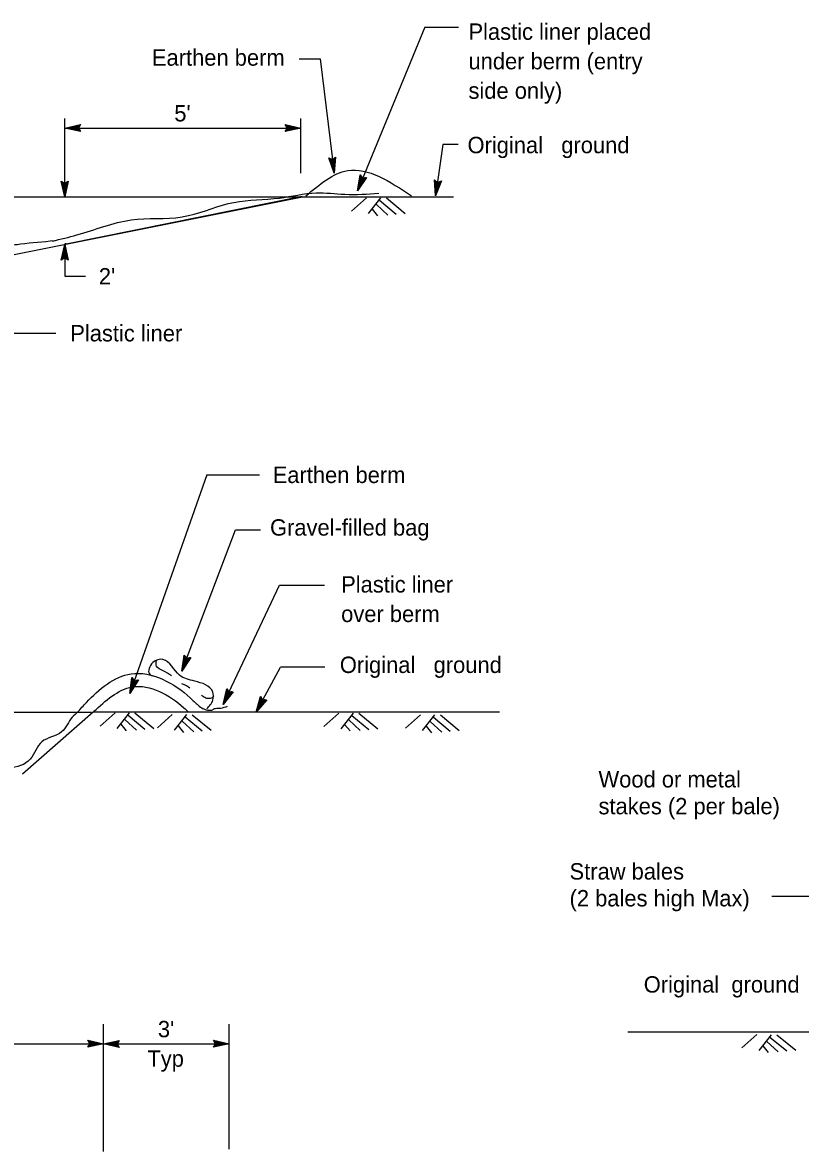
# Model space of a CAD drawing. Extents: x 6708826 to 6711089, y 1868571 to 1869537.
# Drawn here: x 6709143.3 to 6709428.3, y 1869105.8 to 1869519.2 of the extents above; entities that cross this region are included whole.
import ezdxf

# ---------------------------------------------------------------- set-up
doc = ezdxf.new("R2010")
doc.units = 0
for name, color, linetype in [('1 Control', 7, 'Continuous'), ('56 Stg 3 Anno', 7, 'Continuous'), ('57 Undefined', 7, 'Continuous'), ('59 Soundwall Ann', 7, 'Continuous'), ('60 Nongeo Data', 7, 'Continuous')]:
    doc.layers.add(name, color=color, linetype=linetype)

msp = doc.modelspace()

# ---------------------------------------------------------------- linework, layer by layer
at = {"layer": '1 Control'}
for p, q in [((6709267.01, 1869463.37), (6709267.01, 1869463.37)), ((6709269.37, 1869462.4), (6709269.37, 1869462.4)), ((6709265.99, 1869457.56), (6709265.99, 1869457.56)), ((6709202.56, 1869287.55), (6709202.56, 1869287.55)), ((6709204.96, 1869286.64), (6709204.96, 1869286.64)), ((6709183.36, 1869279.3), (6709183.36, 1869279.3)), ((6709201.71, 1869281.71), (6709201.71, 1869281.71)), ((6709185.77, 1869278.45), (6709185.77, 1869278.45)), ((6709218.15, 1869275.23), (6709218.15, 1869275.23)), ((6709182.65, 1869273.45), (6709182.65, 1869273.45)), ((6709220.47, 1869274.13), (6709220.47, 1869274.13)), ((6709230.52, 1869272.38), (6709230.52, 1869272.38)), ((6709232.77, 1869271.16), (6709232.77, 1869271.16)), ((6709216.84, 1869269.47), (6709216.84, 1869269.47)), ((6709228.89, 1869266.71), (6709228.89, 1869266.71))]:
    msp.add_line(p, q, dxfattribs=at)
for points in [[(6709269.37, 1869462.4), (6709265.99, 1869457.56), (6709267, 1869463.38), (6709267.24, 1869463.06), (6709266.49, 1869458.8), (6709268.98, 1869462.34), (6709268.59, 1869462.28), (6709267, 1869460.01), (6709267.48, 1869462.74), (6709267.71, 1869462.42), (6709267.51, 1869461.24), (6709268.2, 1869462.22), (6709267.89, 1869462.18), (6709267, 1869463.38), (6709267.89, 1869462.18)], [(6709204.96, 1869286.64), (6709201.71, 1869281.71), (6709202.56, 1869287.55), (6709202.81, 1869287.24), (6709202.18, 1869282.96), (6709204.57, 1869286.57), (6709204.18, 1869286.5), (6709202.65, 1869284.19), (6709203.05, 1869286.92), (6709203.3, 1869286.61), (6709203.13, 1869285.43), (6709203.79, 1869286.43), (6709203.48, 1869286.38), (6709202.56, 1869287.55), (6709203.48, 1869286.38)], [(6709185.77, 1869278.45), (6709182.65, 1869273.45), (6709183.35, 1869279.3), (6709183.61, 1869279), (6709183.09, 1869274.71), (6709185.38, 1869278.37), (6709185, 1869278.29), (6709183.53, 1869275.95), (6709183.86, 1869278.69), (6709184.11, 1869278.38), (6709183.97, 1869277.2), (6709184.61, 1869278.22), (6709184.3, 1869278.15), (6709183.35, 1869279.3), (6709184.3, 1869278.15)], [(6709220.47, 1869274.13), (6709216.84, 1869269.47), (6709218.15, 1869275.23), (6709218.37, 1869274.9), (6709217.41, 1869270.68), (6709220.07, 1869274.1), (6709219.68, 1869274.06), (6709217.98, 1869271.87), (6709218.59, 1869274.57), (6709218.81, 1869274.24), (6709218.55, 1869273.07), (6709219.28, 1869274.02), (6709218.98, 1869273.99), (6709218.15, 1869275.23), (6709218.98, 1869273.99)], [(6709232.77, 1869271.16), (6709228.89, 1869266.71), (6709230.52, 1869272.38), (6709230.72, 1869272.04), (6709229.53, 1869267.88), (6709232.37, 1869271.14), (6709231.98, 1869271.12), (6709230.16, 1869269.04), (6709230.92, 1869271.7), (6709231.12, 1869271.35), (6709230.79, 1869270.2), (6709231.58, 1869271.11), (6709231.27, 1869271.1), (6709230.52, 1869272.38), (6709231.27, 1869271.1)]]:
    msp.add_lwpolyline(points, close=True, dxfattribs=at)
msp.add_spline([(6709209.29, 1869267.99), (6709211.08, 1869267.44), (6709212.61, 1869267.44), (6709213.63, 1869267.95), (6709215.32, 1869268.12), (6709217.86, 1869268.63), (6709218.37, 1869268.8)], degree=3, dxfattribs=at)
at = {"layer": '56 Stg 3 Anno'}
for p, q in [((6709290.72, 1869517.49), (6709265.99, 1869457.56)), ((6709290.72, 1869517.49), (6709302.98, 1869517.49)), ((6709244.61, 1869505.89), (6709252.38, 1869505.89)), ((6709252.38, 1869505.89), (6709257.43, 1869464.09)), ((6709158.78, 1869455.4), (6709158.78, 1869484.01)), ((6709158.78, 1869480.58), (6709164.54, 1869481.86)), ((6709164.54, 1869481.86), (6709163.78, 1869480.58)), ((6709164.54, 1869481.86), (6709164.54, 1869481.86)), ((6709240.33, 1869480.58), (6709239.56, 1869481.87)), ((6709239.56, 1869481.87), (6709239.56, 1869481.87)), ((6709239.56, 1869481.87), (6709245.32, 1869480.58)), ((6709245.32, 1869464.09), (6709245.32, 1869484.01)), ((6709158.78, 1869480.58), (6709245.32, 1869480.58)), ((6709164.54, 1869479.29), (6709158.78, 1869480.58)), ((6709158.78, 1869480.58), (6709158.78, 1869480.58)), ((6709164.34, 1869479.64), (6709160.11, 1869480.58)), ((6709160.12, 1869480.58), (6709164.32, 1869481.51)), ((6709161.44, 1869480.58), (6709164.15, 1869481.18)), ((6709164.11, 1869479.98), (6709161.44, 1869480.58)), ((6709162.76, 1869480.58), (6709163.92, 1869480.83)), ((6709163.94, 1869480.31), (6709162.76, 1869480.58)), ((6709163.78, 1869480.58), (6709164.54, 1869479.29)), ((6709164.54, 1869479.29), (6709164.54, 1869479.29)), ((6709245.32, 1869480.58), (6709239.56, 1869479.3)), ((6709239.56, 1869479.3), (6709240.33, 1869480.58)), ((6709239.56, 1869479.3), (6709239.56, 1869479.3)), ((6709239.77, 1869481.52), (6709243.99, 1869480.58)), ((6709243.98, 1869480.58), (6709239.78, 1869479.65)), ((6709242.67, 1869480.58), (6709239.95, 1869479.98)), ((6709239.99, 1869481.18), (6709242.67, 1869480.58)), ((6709240.16, 1869480.85), (6709241.34, 1869480.58)), ((6709241.34, 1869480.58), (6709240.18, 1869480.33)), ((6709245.32, 1869480.58), (6709245.32, 1869480.58)), ((6709297.29, 1869474.56), (6709294.59, 1869455.69)), ((6709302.88, 1869474.56), (6709297.29, 1869474.56)), ((6709257.43, 1869464.09), (6709255.47, 1869469.65)), ((6709255.47, 1869469.65), (6709255.47, 1869469.65)), ((6709255.47, 1869469.65), (6709256.83, 1869469.04)), ((6709257.26, 1869465.41), (6709255.84, 1869469.47)), ((6709257.11, 1869466.72), (6709256.19, 1869469.34)), ((6709256.83, 1869469.04), (6709258.01, 1869469.96)), ((6709257.38, 1869469.45), (6709257.11, 1869466.72)), ((6709257.7, 1869469.71), (6709257.27, 1869465.4)), ((6709258.01, 1869469.96), (6709257.43, 1869464.09)), ((6709258.01, 1869469.96), (6709258.01, 1869469.96)), ((6709256.95, 1869468.04), (6709256.56, 1869469.16)), ((6709257.07, 1869469.24), (6709256.95, 1869468.04)), ((6709158.78, 1869455.4), (6709157.51, 1869461.16)), ((6709157.51, 1869461.16), (6709157.51, 1869461.16)), ((6709157.51, 1869461.16), (6709158.78, 1869460.39)), ((6709158.78, 1869460.39), (6709160.07, 1869461.16)), ((6709160.07, 1869461.16), (6709158.78, 1869455.4)), ((6709160.07, 1869461.16), (6709160.07, 1869461.16)), ((6709257.43, 1869464.09), (6709257.43, 1869464.09)), ((6709294.59, 1869455.69), (6709294.2, 1869461.57)), ((6709294.2, 1869461.57), (6709294.2, 1869461.57)), ((6709294.2, 1869461.57), (6709295.34, 1869460.62)), ((6709294.79, 1869457.01), (6709294.5, 1869461.3)), ((6709296.73, 1869461.18), (6709294.59, 1869455.69)), ((6709296.36, 1869461.03), (6709294.79, 1869456.99)), ((6709294.99, 1869458.31), (6709294.81, 1869461.08)), ((6709295.34, 1869460.62), (6709296.73, 1869461.18)), ((6709296.73, 1869461.18), (6709296.73, 1869461.18)), ((6709158.78, 1869456.74), (6709157.85, 1869460.94)), ((6709158.79, 1869458.05), (6709158.18, 1869460.77)), ((6709158.79, 1869459.38), (6709158.53, 1869460.54)), ((6709159.73, 1869460.95), (6709158.78, 1869456.73)), ((6709159.38, 1869460.73), (6709158.79, 1869458.05)), ((6709159.05, 1869460.56), (6709158.79, 1869459.38)), ((6709295.99, 1869460.86), (6709294.99, 1869458.31)), ((6709295.19, 1869459.62), (6709295.11, 1869460.8)), ((6709295.63, 1869460.74), (6709295.19, 1869459.62)), ((6709158.78, 1869455.4), (6709158.78, 1869455.4)), ((6709294.59, 1869455.69), (6709294.59, 1869455.69)), ((6709157.5, 1869432.22), (6709158.78, 1869437.98)), ((6709157.84, 1869432.42), (6709158.78, 1869436.65)), ((6709158.78, 1869437.98), (6709158.78, 1869426.29)), ((6709158.78, 1869437.98), (6709158.78, 1869437.98)), ((6709158.78, 1869437.98), (6709160.06, 1869432.22)), ((6709158.79, 1869436.64), (6709159.72, 1869432.44)), ((6709158.78, 1869432.98), (6709157.5, 1869432.22)), ((6709157.5, 1869432.22), (6709157.5, 1869432.22)), ((6709158.18, 1869432.65), (6709158.78, 1869435.32)), ((6709158.52, 1869432.82), (6709158.78, 1869434)), ((6709158.78, 1869435.32), (6709159.38, 1869432.61)), ((6709158.78, 1869434), (6709159.04, 1869432.84)), ((6709160.06, 1869432.22), (6709158.78, 1869432.98)), ((6709160.06, 1869432.22), (6709160.06, 1869432.22)), ((6709158.78, 1869426.29), (6709166.42, 1869426.29)), ((6709127.18, 1869405.43), (6709155.5, 1869405.43)), ((6709210.84, 1869353.56), (6709182.65, 1869273.45)), ((6709210.84, 1869353.56), (6709230.11, 1869353.56)), ((6709201.71, 1869281.71), (6709221.36, 1869333.46)), ((6709221.36, 1869333.46), (6709230.52, 1869333.46)), ((6709216.84, 1869269.47), (6709237.5, 1869313.21)), ((6709237.5, 1869313.21), (6709253.96, 1869313.21)), ((6709228.89, 1869266.71), (6709237.82, 1869283.16)), ((6709254, 1869283.16), (6709237.82, 1869283.16)), ((6709493.42, 1869199.11), (6709417.73, 1869199.11)), ((6709173.02, 1869105.81), (6709173.02, 1869152.41)), ((6709219.07, 1869131.11), (6709219.07, 1869152.41)), ((6708957.34, 1869145.21), (6709173.02, 1869145.21)), ((6709168.03, 1869145.21), (6709167.26, 1869146.5)), ((6709167.26, 1869146.5), (6709167.26, 1869146.5)), ((6709167.26, 1869146.5), (6709173.02, 1869145.21)), ((6709173.02, 1869145.21), (6709167.26, 1869143.93)), ((6709167.26, 1869143.93), (6709168.03, 1869145.21)), ((6709167.26, 1869143.93), (6709167.26, 1869143.93)), ((6709167.47, 1869146.15), (6709171.7, 1869145.21)), ((6709171.69, 1869145.21), (6709167.49, 1869144.28)), ((6709170.37, 1869145.21), (6709167.66, 1869144.61)), ((6709167.7, 1869145.81), (6709170.37, 1869145.21)), ((6709167.87, 1869145.48), (6709169.05, 1869145.21)), ((6709169.05, 1869145.21), (6709167.89, 1869144.96)), ((6709173.02, 1869145.21), (6709178.78, 1869146.49)), ((6709173.02, 1869145.21), (6709219.07, 1869145.21)), ((6709173.02, 1869145.21), (6709173.02, 1869145.21)), ((6709178.78, 1869143.92), (6709173.02, 1869145.21)), ((6709173.02, 1869145.21), (6709173.02, 1869145.21)), ((6709178.58, 1869144.27), (6709174.35, 1869145.21)), ((6709174.36, 1869145.21), (6709178.56, 1869146.14)), ((6709175.68, 1869145.21), (6709178.39, 1869145.81)), ((6709178.35, 1869144.61), (6709175.68, 1869145.21)), ((6709177, 1869145.21), (6709178.16, 1869145.46)), ((6709178.18, 1869144.94), (6709177, 1869145.21)), ((6709178.78, 1869146.49), (6709178.02, 1869145.21)), ((6709178.02, 1869145.21), (6709178.78, 1869143.92)), ((6709178.78, 1869146.49), (6709178.78, 1869146.49)), ((6709178.78, 1869143.92), (6709178.78, 1869143.92)), ((6709214.07, 1869145.21), (6709213.31, 1869146.5)), ((6709213.31, 1869146.5), (6709213.31, 1869146.5)), ((6709213.31, 1869146.5), (6709219.07, 1869145.21)), ((6709219.07, 1869145.21), (6709213.31, 1869143.93)), ((6709213.31, 1869143.93), (6709214.07, 1869145.21)), ((6709213.31, 1869143.93), (6709213.31, 1869143.93)), ((6709213.51, 1869146.15), (6709217.74, 1869145.21)), ((6709217.73, 1869145.21), (6709213.53, 1869144.28)), ((6709216.41, 1869145.21), (6709213.7, 1869144.61)), ((6709213.74, 1869145.81), (6709216.41, 1869145.21)), ((6709213.91, 1869145.48), (6709215.09, 1869145.21)), ((6709215.09, 1869145.21), (6709213.93, 1869144.96)), ((6709219.07, 1869145.21), (6709219.07, 1869145.21)), ((6709219.07, 1869106.58), (6709219.07, 1869133.32))]:
    msp.add_line(p, q, dxfattribs=at)
at = {"layer": '59 Soundwall Ann'}
for p, q in [((6709269.3, 1869455.02), (6709263.82, 1869450.15)), ((6709274.5, 1869454.98), (6709269.98, 1869449.24)), ((6709274.05, 1869454.12), (6709280.24, 1869449.03)), ((6709276.6, 1869454.96), (6709283.53, 1869449.26)), ((6709271.42, 1869450.89), (6709273.4, 1869448.46)), ((6709272.92, 1869452.54), (6709277.15, 1869448.69)), ((6709177.22, 1869266.44), (6709171.74, 1869261.56)), ((6709182.41, 1869266.4), (6709177.9, 1869260.65)), ((6709180.84, 1869263.95), (6709185.06, 1869260.11)), ((6709181.97, 1869265.54), (6709188.16, 1869260.44)), ((6709184.52, 1869266.38), (6709191.44, 1869260.68)), ((6709198.19, 1869265.8), (6709192.71, 1869260.93)), ((6709203.38, 1869265.77), (6709198.87, 1869260.02)), ((6709201.81, 1869263.32), (6709206.03, 1869259.47)), ((6709202.94, 1869264.9), (6709209.13, 1869259.81)), ((6709205.49, 1869265.74), (6709212.41, 1869260.04)), ((6709259.2, 1869266.34), (6709253.72, 1869261.46)), ((6709264.39, 1869266.3), (6709259.87, 1869260.55)), ((6709262.81, 1869263.85), (6709267.04, 1869260)), ((6709263.94, 1869265.44), (6709270.13, 1869260.34)), ((6709266.5, 1869266.28), (6709273.42, 1869260.58)), ((6709289.06, 1869265.7), (6709283.58, 1869260.83)), ((6709294.26, 1869265.67), (6709289.74, 1869259.92)), ((6709292.68, 1869263.22), (6709296.91, 1869259.37)), ((6709293.81, 1869264.8), (6709300, 1869259.71)), ((6709296.36, 1869265.64), (6709303.29, 1869259.94)), ((6709179.34, 1869262.3), (6709181.32, 1869259.87)), ((6709200.31, 1869261.67), (6709202.29, 1869259.24)), ((6709261.31, 1869262.2), (6709263.29, 1869259.77)), ((6709291.18, 1869261.57), (6709293.16, 1869259.14)), ((6709412.31, 1869148.59), (6709406.83, 1869143.72)), ((6709417.5, 1869148.55), (6709412.98, 1869142.81)), ((6709417.05, 1869147.69), (6709423.24, 1869142.6)), ((6709419.61, 1869148.53), (6709426.53, 1869142.83)), ((6709414.42, 1869144.46), (6709416.4, 1869142.03)), ((6709415.92, 1869146.11), (6709420.15, 1869142.26))]:
    msp.add_line(p, q, dxfattribs=at)
at = {"layer": '60 Nongeo Data'}
for p, q in [((6708926.44, 1869455.4), (6709246.42, 1869455.4)), ((6709079.54, 1869422.13), (6709245.91, 1869455.4)), ((6709159.31, 1869438.15), (6709245.73, 1869455.6)), ((6709245.93, 1869455.42), (6709301.24, 1869455.4)), ((6709159.31, 1869438.15), (6709158.84, 1869438.19)), ((6709100.59, 1869266.71), (6709168.62, 1869266.71)), ((6709169.25, 1869266.71), (6709143.34, 1869243.93)), ((6709318.02, 1869266.71), (6709169.25, 1869266.71)), ((6709365.05, 1869149.57), (6709494.96, 1869149.57))]:
    msp.add_line(p, q, dxfattribs=at)
for points in [[(6709247.09, 1869455.75), (6709262.42, 1869465), (6709285.84, 1869455.72)], [(6709154.27, 1869439.18), (6709163.26, 1869441.4), (6709183.16, 1869446.94), (6709201.75, 1869448.04), (6709204.06, 1869448.49), (6709220.76, 1869453.35), (6709237.4, 1869454.94), (6709250.83, 1869456.82), (6709261.39, 1869456.32), (6709273.82, 1869456.69)], [(6709155.03, 1869439.22), (6709142.61, 1869438.01), (6709137.51, 1869437.25), (6709118.63, 1869431.78), (6709098.86, 1869429.66), (6709092.64, 1869427.99), (6709077.2, 1869424.09), (6709067.17, 1869423.66), (6709051.11, 1869425.1), (6709040.55, 1869425.74), (6709027.92, 1869424.04), (6709018.17, 1869423.86)], [(6709210.81, 1869267.86), (6709213.02, 1869271.09), (6709212.98, 1869274.12), (6709206.38, 1869278.03), (6709200.85, 1869280.2), (6709194.76, 1869285.94), (6709191.05, 1869284.82), (6709189.91, 1869280.59), (6709190.88, 1869279.96)], [(6709197.88, 1869279.91), (6709194.78, 1869281.84), (6709192.4, 1869283.55), (6709192.34, 1869285.52)], [(6709163.52, 1869266.68), (6709166.75, 1869270.26), (6709183.08, 1869280.71), (6709204.79, 1869271.86), (6709207.63, 1869269.23), (6709209.48, 1869267.86)], [(6709169.21, 1869266.71), (6709169.5, 1869266.97), (6709183.52, 1869275.93), (6709202.46, 1869268.22), (6709204, 1869266.75)], [(6709204.59, 1869275.5), (6709202.89, 1869276.56), (6709201.71, 1869277.09)], [(6709213.39, 1869272.37), (6709212.09, 1869271.67), (6709210.47, 1869271.83), (6709208.92, 1869272.79)], [(6709163.61, 1869266.78), (6709161.57, 1869264.84), (6709157.64, 1869259.41), (6709150.39, 1869255.79), (6709146.16, 1869249.46), (6709138.31, 1869246.15), (6709117.17, 1869249.16), (6709106.9, 1869247.35), (6709095.12, 1869247.35), (6709084.24, 1869249.16), (6709070.65, 1869246.75), (6709059.78, 1869246.75), (6709051.02, 1869249.16), (6709041.66, 1869248.56), (6709034.11, 1869246.75), (6709023.53, 1869246.15), (6709014.78, 1869248.26), (6709003.9, 1869249.16), (6708994.24, 1869246.75), (6708986.99, 1869246.75), (6708979.74, 1869247.96), (6708976.12, 1869252.18), (6708967.66, 1869258.2), (6708963.43, 1869265.14), (6708959.5, 1869265.74), (6708958.51, 1869266.68)]]:
    msp.add_spline(points, degree=3, dxfattribs=at)

# ---------------------------------------------------------------- texts
at = {"layer": '57 Undefined'}
for s, p in [('Plastic liner placed ', (6709306.67, 1869512.87)), ('Earthen berm', (6709190.72, 1869503.39)), ('under berm (entry ', (6709306.67, 1869502.07)), ('side only)', (6709306.67, 1869491.27)), ("5'", (6709198.92, 1869482.98)), ('Original   ground', (6709306.32, 1869471.35)), ("2'", (6709171.28, 1869423.29)), ('Plastic liner', (6709160.82, 1869402.43)), ('Earthen berm', (6709234.96, 1869350.56)), ('Gravel-filled bag', (6709233.98, 1869331.31)), ('Plastic liner', (6709260.03, 1869310.46)), ('over berm', (6709260.03, 1869299.66)), ('Original   ground', (6709259.55, 1869281.01)), ('Wood or metal ', (6709354.29, 1869239.1)), ('stakes (2 per bale)', (6709354.29, 1869229.26)), ('Straw bales', (6709343.69, 1869205.37)), ('(2 bales high Max)', (6709343.69, 1869195.53)), ('Original  ground', (6709370.86, 1869163.97)), ("3'", (6709192.91, 1869147.61)), ('Typ', (6709189.06, 1869136.81))]:
    msp.add_text(s, height=6, dxfattribs=at).set_placement(p)

doc.saveas('drawing.dxf')
